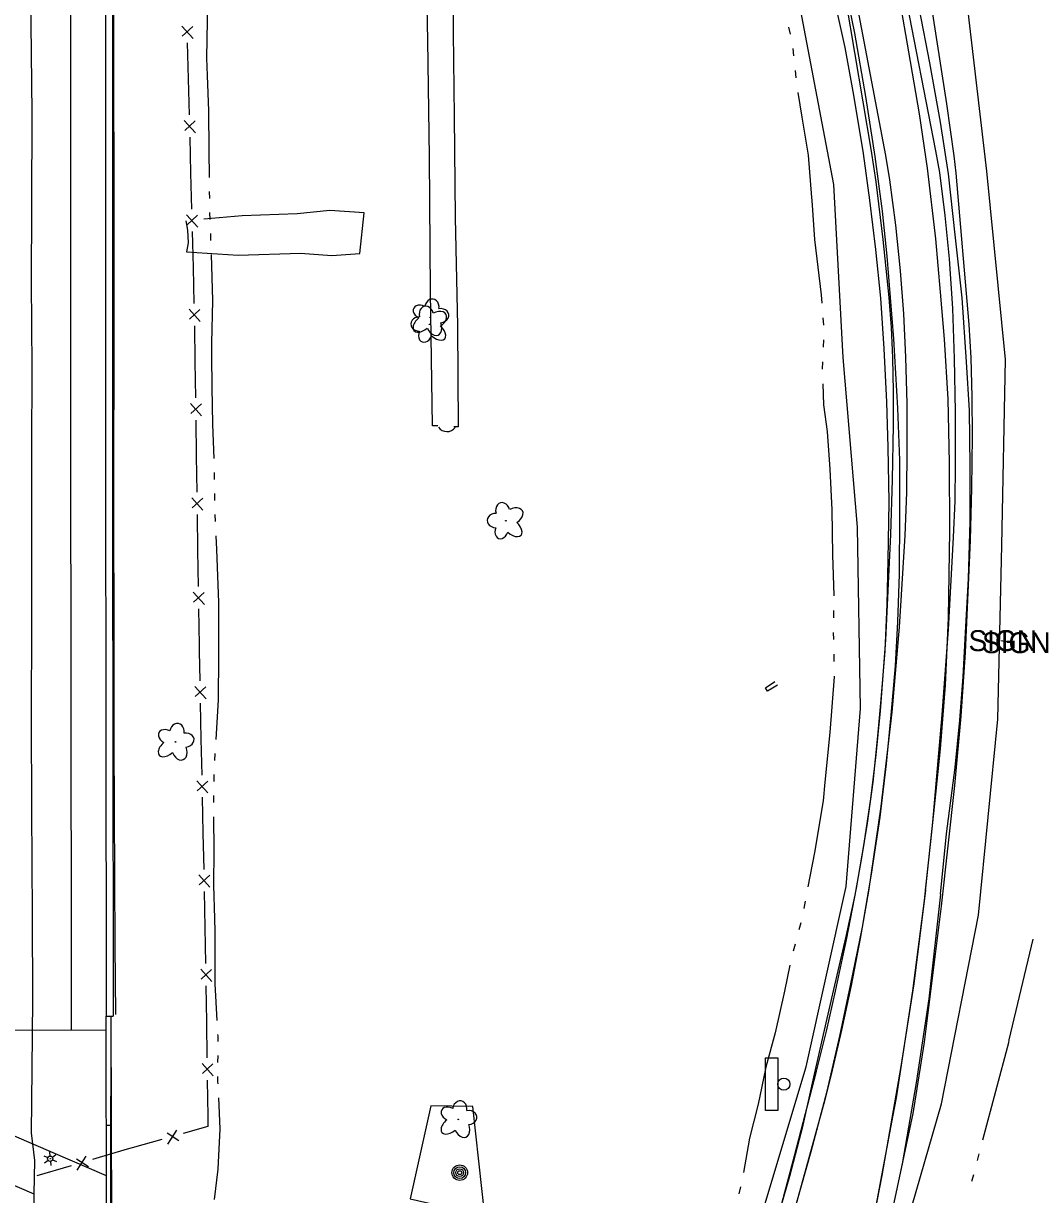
# Model space of a CAD drawing. Extents: x 588843 to 2552415, y 180129 to 269402.
# Drawn here: x 594066 to 594355.6, y 185595.1 to 185930.2 of the extents above; entities that cross this region are included whole.
import ezdxf

# ---------------------------------------------------------------- set-up
doc = ezdxf.new("R2010")
doc.units = 0
for name, color, linetype in [('Default', 7, 'Continuous'), ('E_AREA', 7, 'Continuous'), ('E_DRN', 7, 'Continuous'), ('E_DRN_RipRap', 7, 'Continuous'), ('E_FEN_P', 7, 'Continuous'), ('E_LAND_TreeLine', 7, 'Continuous'), ('E_LAND_Vegetation', 7, 'Continuous'), ('E_LTG', 7, 'Continuous'), ('E_MISCPROP', 7, 'Continuous'), ('E_RDWY', 7, 'Continuous'), ('E_RDWY_AsphConc', 7, 'Continuous'), ('E_RDWY_BarrierConc', 7, 'Continuous'), ('E_RDWY_Gravel', 7, 'Continuous'), ('E_RDWY_PavtEdge', 7, 'Continuous'), ('E_SGN', 7, 'Continuous'), ('E_STRUCT', 7, 'Continuous'), ('E_WTR_P', 7, 'Continuous'), ('P_RDWY_BarrierConc', 7, 'Continuous'), ('P_RDWY_PavtEdge', 7, 'Continuous'), ('P_STRUCT', 7, 'Continuous')]:
    doc.layers.add(name, color=color, linetype=linetype)

# ---------------------------------------------------------------- blocks, each defined once
blk = doc.blocks.new('DTRE_1_1')
at = {"layer": 'Default'}
blk.add_circle((-0.18, 0), 0.183, dxfattribs=at)
for centre, major_axis, ratio in [((-1.87, 5.32), (1.36, -4.98), 0.782863), ((4.06, 2.74), (-5.27, -2.93), 0.691916), ((-5.87, 0.15), (4.93, -0.12), 0.832022), ((-2.49, -5.24), (1.8, 4.86), 0.716896), ((3.54, -3.71), (-5.01, 4.58), 0.560249)]:
    blk.add_ellipse(centre, major_axis=major_axis, ratio=ratio, start_param=1.570796, end_param=4.712389, dxfattribs=at)
blk = doc.blocks.new('BSGN_1')
at = {"layer": 'Default'}
blk.add_text('SIGN', height=12, dxfattribs=at).set_placement((-18.56, -6))
blk = doc.blocks.new('SGN_1')
at = {"layer": 'Default'}
blk.add_lwpolyline([(-3.5, -15), (-10.5, -15), (-10.5, 15), (-3.5, 15)], close=True, dxfattribs=at)
blk.add_circle((0, 0), 3.5, dxfattribs=at)
blk = doc.blocks.new('CULV2_4')
at = {"layer": 'E_DRN'}
blk.add_arc((64.6, 48.4), 80.7, 216.8699, 323.1301, dxfattribs=at)
blk = doc.blocks.new('LPOL_4')
at = {"layer": 'E_LTG'}
for p, q in [((-13.1, 0), (-4.9, 0)), ((-2.5, 4.3), (-6.6, 11.4)), ((2.5, 4.3), (6.6, 11.4)), ((4.9, 0), (13.1, 0)), ((-6.6, -11.4), (-2.5, -4.3)), ((6.6, -11.4), (2.5, -4.3))]:
    blk.add_line(p, q, dxfattribs=at)
for radius in [4.92, 4.92, 4.92, 0.41]:
    blk.add_circle((0, 0), radius, dxfattribs=at)
blk = doc.blocks.new('POLE_3')
at = {"layer": 'E_MISCPROP'}
for radius in [14.6, 11, 7.32, 3.66]:
    blk.add_circle((0, 0), radius, dxfattribs=at)
blk = doc.blocks.new('DTRE_4')
at = {"layer": 'E_LAND_Vegetation'}
blk.add_circle((-0.6, 0), 0.601, dxfattribs=at)
for centre, major_axis, ratio in [((-6.1, 17.5), (4.5, -16.3), 0.782863), ((13.3, 9), (-17.3, -9.6), 0.691916), ((-19.3, 0.5), (16.2, -0.4), 0.832022), ((-8.2, -17.2), (5.9, 15.9), 0.716896), ((11.6, -12.2), (-16.4, 15), 0.560249)]:
    blk.add_ellipse(centre, major_axis=major_axis, ratio=ratio, start_param=1.570796, end_param=4.712389, dxfattribs=at)

msp = doc.modelspace()

# ---------------------------------------------------------------- linework, layer by layer
at = {"layer": 'E_AREA'}
msp.add_lwpolyline([(594184.55, 185815.05), (594183.08, 185815.03), (594182.48, 185853.37), (594182.16, 185891.99), (594181.73, 185925.3), (594181.17, 185954.3), (594180.32, 185981.29), (594180.18, 185990.94), (594187.61, 185990.93), (594188.86, 185966.43), (594189.07, 185947.36), (594188.94, 185927.54), (594189.25, 185903.49), (594189.55, 185874.61), (594190.24, 185843.6), (594190.34, 185814.77), (594189.16, 185814.75)], dxfattribs=at)
at = {"layer": 'E_DRN_RipRap'}
msp.add_lwpolyline([(594112.48, 185873.68), (594112.89, 185871.02), (594113.1, 185867.43), (594112.61, 185864.78), (594127.38, 185863.84), (594145.28, 185864.4), (594154.19, 185863.74), (594162.26, 185864.38), (594163.49, 185875.95), (594153.67, 185876.61), (594144.29, 185875.66), (594128.58, 185875.15), (594117.6, 185874.19)], dxfattribs=at)
at = {"layer": 'E_FEN_P'}
for p, q in [((594111.29, 185929.35), (594114.51, 185925.84)), ((594114.42, 185929.27), (594111.43, 185926.49)), ((594111.98, 185902.37), (594115.2, 185898.86)), ((594115.11, 185902.29), (594112.12, 185899.51)), ((594112.67, 185875.39), (594115.88, 185871.89)), ((594115.8, 185875.31), (594112.81, 185872.53)), ((594113.37, 185848.43), (594116.55, 185844.89)), ((594116.49, 185848.31), (594113.47, 185845.57)), ((594113.77, 185821.45), (594116.94, 185817.91)), ((594116.89, 185821.33), (594113.87, 185818.59)), ((594114.17, 185794.46), (594117.34, 185790.92)), ((594117.29, 185794.35), (594114.27, 185791.6)), ((594114.57, 185767.48), (594117.74, 185763.94)), ((594117.69, 185767.36), (594114.67, 185764.62)), ((594115.02, 185740.49), (594118.22, 185736.97)), ((594118.15, 185740.39), (594115.15, 185737.63)), ((594115.58, 185713.51), (594118.78, 185709.99)), ((594118.71, 185713.41), (594115.71, 185710.65)), ((594116.14, 185686.53), (594119.34, 185683.01)), ((594119.27, 185686.43), (594116.27, 185683.67)), ((594116.7, 185659.56), (594119.87, 185656.01)), ((594119.83, 185659.44), (594116.8, 185656.69)), ((594117.08, 185632.57), (594120.26, 185629.03)), ((594120.21, 185632.45), (594117.18, 185629.71)), ((594110.48, 185610.47), (594107.06, 185612.69)), ((594109.8, 185613.53), (594107.18, 185609.55)), ((594084.57, 185603.03), (594081.11, 185605.2)), ((594083.84, 185606.08), (594081.28, 185602.06))]:
    msp.add_line(p, q, dxfattribs=at)
for points in [[(594112.86, 185924.59), (594113.12, 185914.29)], [(594113.12, 185914.29), (594113.38, 185903.99)], [(594113.55, 185897.62), (594113.81, 185887.32)], [(594113.81, 185887.32), (594114.07, 185877.02)], [(594114.23, 185870.64), (594114.5, 185860.34)], [(594114.5, 185860.34), (594114.76, 185850.04)], [(594114.88, 185843.66), (594115.03, 185833.36)], [(594115.03, 185833.36), (594115.19, 185823.06)], [(594115.28, 185816.68), (594115.43, 185806.37)], [(594115.43, 185806.37), (594115.59, 185796.07)], [(594115.68, 185789.69), (594115.83, 185779.39)], [(594115.83, 185779.39), (594115.99, 185769.09)], [(594116.08, 185762.71), (594116.23, 185752.41)], [(594116.23, 185752.41), (594116.26, 185750.57), (594116.44, 185742.11)], [(594116.57, 185735.73), (594116.78, 185725.43)], [(594116.78, 185725.43), (594116.99, 185715.12)], [(594117.13, 185708.75), (594117.34, 185698.45)], [(594117.34, 185698.45), (594117.55, 185688.14)], [(594117.68, 185681.77), (594117.9, 185671.47)], [(594117.9, 185671.47), (594118.11, 185661.16)], [(594118.21, 185654.79), (594118.35, 185644.48)], [(594118.35, 185644.48), (594118.5, 185634.18)], [(594118.59, 185627.8), (594118.74, 185617.5)], [(594118.74, 185617.5), (594118.78, 185614.53), (594111.71, 185612.56)], [(594105.57, 185610.85), (594097.08, 185608.48), (594095.65, 185608.06)], [(594095.65, 185608.06), (594085.77, 185605.14)], [(594079.65, 185603.34), (594069.77, 185600.42)]]:
    msp.add_lwpolyline(points, dxfattribs=at)
at = {"layer": 'E_LAND_TreeLine'}
msp.add_lwpolyline([(594176.65, 185593.9), (594198.05, 185589.01), (594194.61, 185620.33), (594182.56, 185620.47)], close=True, dxfattribs=at)
at = {"layer": 'E_RDWY'}
for points in [[(594324.17, 185682.16), (594325.63, 185696.1), (594327.06, 185709.65), (594328.41, 185722.6), (594329.84, 185740.85), (594330.72, 185760.06), (594331.14, 185784.99), (594331.05, 185804.48), (594330.65, 185822.65), (594329.6, 185839.87), (594328.47, 185853.26), (594327.07, 185868.5), (594324.68, 185888.72), (594322.39, 185904.29), (594319.39, 185922.01), (594316.84, 185936.3), (594312.06, 185959.24), (594308.86, 185974.75), (594305.12, 185990.37), (594300.05, 186011.89), (594293.22, 186040.84), (594288.78, 186059.3)], [(594287.1, 185592.27), (594291.4, 185607.41), (594295.98, 185624.65), (594299.58, 185640.41), (594302.78, 185655.41), (594306.09, 185671.6), (594308.66, 185686.75), (594311.13, 185703.1), (594312.98, 185718.35), (594314.35, 185732.26), (594315.54, 185746.38), (594316.22, 185758.94), (594316.68, 185772.61), (594316.81, 185789.57), (594316.77, 185805.24), (594316.24, 185820.1), (594315.09, 185839.96), (594313.19, 185863.56), (594311.85, 185876.43), (594309.7, 185892.08), (594307.08, 185909.22), (594303.9, 185927.33), (594300.21, 185945.58)], [(594324.17, 185682.16), (594320.81, 185655.37), (594317.12, 185631.75), (594311.67, 185600.54), (594306.1, 185572.14), (594301.18, 185549.59), (594298.74, 185541.78), (594296.77, 185533.44)]]:
    msp.add_lwpolyline(points, dxfattribs=at)
at = {"layer": 'E_RDWY_AsphConc'}
for points in [[(594311.63, 185576.09), (594320.56, 185618.33), (594320.56, 185618.33), (594321.22, 185621.8), (594321.22, 185621.8), (594323.83, 185638.71), (594323.83, 185638.71), (594328.69, 185677.65), (594328.69, 185677.65), (594332.5, 185712.17), (594332.5, 185712.17), (594334.37, 185731.99), (594334.37, 185731.99), (594335.61, 185750.2), (594335.61, 185750.2), (594337.01, 185782.36), (594337.01, 185782.36), (594337.41, 185797.22), (594337.58, 185812.09), (594337.58, 185812.09), (594337.51, 185823.31), (594337.22, 185834.53), (594337.22, 185834.53), (594336.66, 185843.99), (594336.66, 185843.99), (594332.9, 185887.32), (594332.9, 185887.32), (594332.33, 185892.32), (594332.33, 185892.32), (594330.21, 185907.13), (594330.21, 185907.13), (594325.09, 185940.38)], [(594280.62, 185583.6), (594286.69, 185606.22), (594286.69, 185606.22), (594292.98, 185630.36), (594292.98, 185630.36), (594295.8, 185641.81), (594298.41, 185653.31), (594298.41, 185653.31), (594301.5, 185668.02), (594304.37, 185682.77), (594304.37, 185682.77), (594306.59, 185695.5), (594308.5, 185708.29), (594308.5, 185708.29), (594310.06, 185720.88), (594311.3, 185733.5), (594311.3, 185733.5), (594312.75, 185753.76), (594312.75, 185753.76), (594314.18, 185783.94), (594314.18, 185783.94), (594314.67, 185799.58), (594314.96, 185815.22), (594314.96, 185815.22), (594314.97, 185824.87), (594314.78, 185834.52), (594314.78, 185834.52), (594314.37, 185843.17), (594313.69, 185851.79), (594313.69, 185851.79), (594311.99, 185868.33), (594310, 185884.84), (594310, 185884.84), (594308.71, 185893.65), (594308.71, 185893.65), (594301.56, 185935.95)], [(594281.8, 185740.81), (594278.92, 185739.16), (594278.33, 185740.05), (594280.97, 185741.93)]]:
    msp.add_lwpolyline(points, dxfattribs=at)
at = {"layer": 'E_RDWY_BarrierConc'}
msp.add_lwpolyline([(594092.41, 185646.59), (594092.23, 185666.33), (594091.89, 185724.73), (594091.96, 185748.56), (594091.86, 185797.61), (594091.91, 185841.47), (594091.93, 185867.8), (594091.87, 185930.74), (594091.81, 185977.86), (594091.82, 186024.62), (594091.91, 186074.39)], dxfattribs=at)
at = {"layer": 'E_RDWY_Gravel'}
for points in [[(594303.67, 185543.21), (594315.42, 185575.19), (594328.72, 185621.05), (594339.34, 185675.01), (594344.82, 185731.08), (594346, 185780.82), (594347.01, 185834), (594341.7, 185887.89), (594335.33, 185942.61), (594336.62, 185994.39), (594331.61, 186011.74), (594326.07, 186040.96), (594313.1, 186096.24)], [(594219.98, 185483.23), (594225.88, 185478.25), (594235.55, 185483.6), (594242.27, 185495.24), (594260.56, 185538.25), (594266.9, 185556.83), (594275.61, 185583.63), (594290, 185631.68), (594301.4, 185683.27), (594305.51, 185734.14), (594304.66, 185786.05), (594300.56, 185834.6), (594297.92, 185884.09), (594288.32, 185934.22), (594278.96, 185984.3), (594268.73, 186024.87), (594254.98, 186086.09)], [(594328.46, 185681.03), (594330.19, 185698.34), (594332.59, 185717.28), (594333.97, 185730.8), (594334.91, 185743.24), (594335.71, 185757.61), (594336.42, 185771.29), (594336.89, 185787.69), (594336.91, 185803.53), (594336.69, 185819.42), (594335.88, 185833.34), (594334.6, 185851.64), (594332.67, 185869.72), (594330.76, 185887.16), (594328.42, 185901.87), (594325.39, 185918.92), (594322.37, 185934.15), (594318.59, 185952.22), (594314.41, 185971.38), (594310.05, 185989.92), (594304.68, 186013.57), (594300.36, 186032.22), (594296.1, 186049.52), (594294.08, 186057.9)], [(594279.79, 185581.31), (594285.33, 185600.37), (594289.12, 185614.95), (594292.19, 185628.65), (594294.96, 185640.92), (594297.94, 185653.77), (594301.4, 185668.91), (594303.98, 185680.78), (594305.94, 185691.42), (594307.52, 185701.32), (594309.17, 185713.05), (594310.51, 185726.29), (594311.42, 185736.77), (594312.57, 185750.62), (594313.16, 185763.88), (594313.44, 185776.64), (594313.77, 185793.28), (594313.48, 185808.97), (594313.07, 185821.81), (594312.35, 185837.17), (594311.35, 185851.57), (594309.95, 185865.46), (594308.24, 185879.59), (594306.35, 185892.99), (594303.62, 185909.61), (594301.18, 185923.26), (594298.52, 185935.32)], [(594328.46, 185681.03), (594325.1, 185651.07), (594321.5, 185627.02), (594317.44, 185603.91), (594313.42, 185585.2), (594306.5, 185557.79), (594302.91, 185543.46), (594299.68, 185544.8)]]:
    msp.add_lwpolyline(points, dxfattribs=at)
at = {"layer": 'E_RDWY_PavtEdge'}
for points in [[(594307.27, 185577.08), (594314.82, 185617.29), (594314.82, 185617.29), (594315.79, 185622.79), (594315.79, 185622.79), (594320.54, 185653.35), (594320.54, 185653.35), (594323.89, 185679.23), (594323.89, 185679.23), (594326.24, 185701.65), (594326.24, 185701.65), (594328.94, 185732.3), (594328.94, 185732.3), (594330.71, 185756.74), (594330.71, 185756.74), (594332.19, 185783.13), (594332.19, 185783.13), (594332.58, 185793.45), (594332.74, 185803.77), (594332.74, 185803.77), (594332.71, 185819.05), (594332.46, 185834.33), (594332.46, 185834.33), (594331.92, 185848.56), (594330.98, 185862.78), (594330.98, 185862.78), (594329.78, 185875.17), (594328.19, 185887.51), (594328.19, 185887.51), (594327.13, 185893.75), (594327.13, 185893.75), (594318.24, 185939.35)], [(594284.5, 185582.85), (594295.38, 185622.31), (594295.38, 185622.31), (594297.22, 185629.41), (594297.22, 185629.41), (594300.22, 185642.12), (594302.96, 185654.9), (594302.96, 185654.9), (594305.57, 185668.36), (594307.92, 185681.87), (594307.92, 185681.87), (594311.49, 185706.13), (594311.49, 185706.13), (594314.61, 185733.08), (594314.61, 185733.08), (594316.73, 185757.43), (594316.73, 185757.43), (594318.3, 185783.7), (594318.3, 185783.7), (594318.75, 185795.96), (594318.93, 185808.22), (594318.93, 185808.22), (594318.85, 185821.44), (594318.51, 185834.65), (594318.51, 185834.65), (594317.9, 185847.05), (594316.95, 185859.42), (594316.95, 185859.42), (594315.61, 185872.41), (594313.93, 185885.37), (594313.93, 185885.37), (594312.76, 185892.42), (594312.76, 185892.42), (594304.37, 185936.52)]]:
    msp.add_lwpolyline(points, dxfattribs=at)
at = {"layer": 'E_SGN'}
msp.add_lwpolyline([(594345.72, 185753.57), (594349.59, 185752.99)], dxfattribs=at)
at = {"layer": 'E_STRUCT'}
for points in [[(594069.19, 185604.81), (594068.28, 185612.73), (594068.5, 185631), (594068.67, 185650.93), (594068.6, 185675.04), (594068.35, 185705.19), (594068.27, 185731.53), (594068.37, 185758.91), (594068.4, 185785.63), (594068.35, 185808.1), (594068.43, 185831.75), (594068.32, 185856.13), (594068.38, 185877.98), (594068.43, 185904.62), (594068.19, 185930), (594068.17, 185953.26), (594068.3, 185981.89), (594068.16, 186006.49), (594068.19, 186032.08), (594068.05, 186060.08), (594068.09, 186085.41), (594068.35, 186116.48), (594068.36, 186116.92)], [(593947.53, 185425.93), (594007.57, 185399.67), (594069.43, 185373.6), (594069.03, 185595.2), (594007.48, 185621.74), (593947.15, 185647.44), (593947.53, 185425.93)], [(594089.61, 185575.54), (594090.86, 185575.71), (594091.08, 185639.18)], [(594069.03, 185595.19), (594069.19, 185604.81)]]:
    msp.add_lwpolyline(points, dxfattribs=at)
at = {"layer": 'E_WTR_P'}
for points in [[(594118.53, 185944.42), (594118.63, 185936.29), (594118.39, 185920.19), (594118.56, 185915.26)], [(594284.91, 185929.08), (594285.44, 185927.05)], [(594286.18, 185922.94), (594286.39, 185920.85)], [(594286.8, 185916.68), (594287.01, 185914.6)], [(594118.56, 185915.26), (594118.93, 185905.18), (594119.05, 185893.79), (594119.12, 185886.12)], [(594287.57, 185910.44), (594288.7, 185903.37), (594290.56, 185892.49), (594291.52, 185880.34)], [(594119.15, 185882.1), (594119.17, 185880.09)], [(594291.52, 185880.34), (594291.59, 185879.49), (594292.36, 185868.33), (594294.29, 185852.5), (594294.46, 185850.1)], [(594119.25, 185876.07), (594119.32, 185874.06)], [(594119.46, 185870.04), (594119.53, 185868.03)], [(594119.67, 185864.01), (594120.07, 185850.91), (594119.78, 185838.66), (594119.81, 185834.86)], [(594294.76, 185845.92), (594294.91, 185843.83)], [(594294.9, 185839.64), (594294.82, 185837.55)], [(594119.81, 185834.86), (594119.88, 185826.15), (594120.1, 185815.44), (594120.42, 185805.71)], [(594294.67, 185833.36), (594294.6, 185831.26)], [(594294.75, 185827.08), (594294.99, 185821.02), (594296.01, 185813.37), (594296.78, 185802.66), (594297.06, 185796.8)], [(594120.51, 185801.69), (594120.55, 185799.68)], [(594297.06, 185796.8), (594297.33, 185790.98), (594297.54, 185778.13), (594297.88, 185766.46), (594297.88, 185766.43)], [(594120.62, 185795.66), (594120.66, 185793.64)], [(594120.78, 185789.62), (594120.87, 185787.62)], [(594121.06, 185783.6), (594121.25, 185779.69), (594121.84, 185764.51), (594121.83, 185754.45)], [(594297.82, 185762.24), (594297.78, 185760.14)], [(594297.72, 185755.95), (594297.77, 185753.86)], [(594121.83, 185754.45), (594121.82, 185749.17), (594121.7, 185736.61), (594120.99, 185725.31)], [(594297.86, 185749.67), (594297.91, 185747.57)], [(594298, 185743.38), (594298, 185743.25), (594296.75, 185727.33), (594295.35, 185713.11)], [(594120.74, 185721.3), (594120.61, 185719.29)], [(594120.44, 185715.27), (594120.42, 185713.26)], [(594295.35, 185713.11), (594294.82, 185707.78), (594292.39, 185692.94), (594290.49, 185683.12)], [(594120.37, 185709.24), (594120.34, 185707.23)], [(594120.32, 185703.21), (594120.42, 185693.53), (594120.41, 185683.6), (594120.62, 185674.05)], [(594289.69, 185679.01), (594289.3, 185676.95)], [(594120.62, 185674.05), (594120.7, 185670.36), (594120.7, 185655.41), (594121.31, 185644.91)], [(594288.47, 185672.84), (594287.92, 185670.82)], [(594286.82, 185666.77), (594286.27, 185664.75)], [(594348.12, 185639.37), (594354.97, 185668.16)], [(594285.27, 185660.68), (594283.77, 185653.26), (594281.14, 185641.39), (594278.46, 185631.59), (594278.35, 185631.1)], [(594121.54, 185640.89), (594121.57, 185640.47), (594121.56, 185638.88)], [(594340.54, 185610.74), (594347.94, 185638.61), (594348.12, 185639.37)], [(594121.56, 185634.86), (594121.55, 185632.85)], [(594121.55, 185628.83), (594121.54, 185627.37), (594121.57, 185626.82)], [(594278.35, 185631.1), (594276.2, 185621), (594273.73, 185611.23), (594272, 185601.42)], [(594121.75, 185622.8), (594122.17, 185613.86), (594121.59, 185602.36), (594120.58, 185593.73)], [(594338.97, 185604.82), (594339.49, 185606.79)], [(594337.39, 185598.9), (594337.48, 185599.21), (594337.92, 185600.87)], [(594271.15, 185597.32), (594270.68, 185595.28)]]:
    msp.add_lwpolyline(points, dxfattribs=at)
at = {"layer": 'P_RDWY_BarrierConc'}
msp.add_line((594089.66, 185646.13), (594091.66, 185646.13), dxfattribs=at)
for radius, end in [(137428.62, 180.1062505), (137426.62, 180.1062503)]:
    msp.add_arc((731518.05, 185900.98), radius, 179.769059, end, dxfattribs=at)
at = {"layer": 'P_RDWY_PavtEdge'}
msp.add_line((594089.68, 185642.14), (594017.68, 185641.99), dxfattribs=at)
msp.add_arc((731518.05, 185900.98), 137438.62, 179.769059, 180.1079132, dxfattribs=at)
at = {"layer": 'P_STRUCT'}
for p, q in [((594089.8, 185581.27), (594089.66, 185646.13)), ((594091.25, 185581.28), (594091.12, 185646.13)), ((594089.76, 185600.41), (594016.24, 185632.16)), ((594091.18, 185614.88), (594089.73, 185614.88))]:
    msp.add_line(p, q, dxfattribs=at)

# ---------------------------------------------------------------- block references
at = {"layer": 'E_DRN', "xscale": 0.03746832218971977, "yscale": 0.03746832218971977, "rotation": -0.9861195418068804}
msp.add_blockref('CULV2_4', (594184.73, 185814.63), dxfattribs=at)
at = {"layer": 'E_LAND_Vegetation', "xscale": 0.1524003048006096, "yscale": 0.1524003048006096, "rotation": -97.36026881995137}
for p in [(594182.4, 185845.96), (594109.47, 185724.51), (594190.4, 185616.52)]:
    msp.add_blockref('DTRE_4', p, dxfattribs=at)
at = {"layer": 'E_LAND_Vegetation', "xscale": 0.5, "yscale": 0.5}
for p in [(594182.25, 185844.07), (594204.11, 185787.87)]:
    msp.add_blockref('DTRE_1_1', p, dxfattribs=at)
at = {"layer": 'E_LTG', "xscale": 0.1524003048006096, "yscale": 0.15240030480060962, "rotation": -84.36014555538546}
msp.add_blockref('LPOL_4', (594073.63, 185605.35), dxfattribs=at)
at = {"layer": 'E_MISCPROP', "xscale": 0.1524003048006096, "yscale": 0.15240030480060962, "rotation": -84.36014555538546}
msp.add_blockref('POLE_3', (594190.83, 185601.37), dxfattribs=at)
at = {"layer": 'E_SGN', "xscale": 0.5, "yscale": 0.5}
for name, p in [('BSGN_1', (594345.72, 185753.57)), ('BSGN_1', (594349.59, 185752.99)), ('SGN_1', (594283.58, 185626.67))]:
    msp.add_blockref(name, p, dxfattribs=at)

doc.saveas('drawing.dxf')
